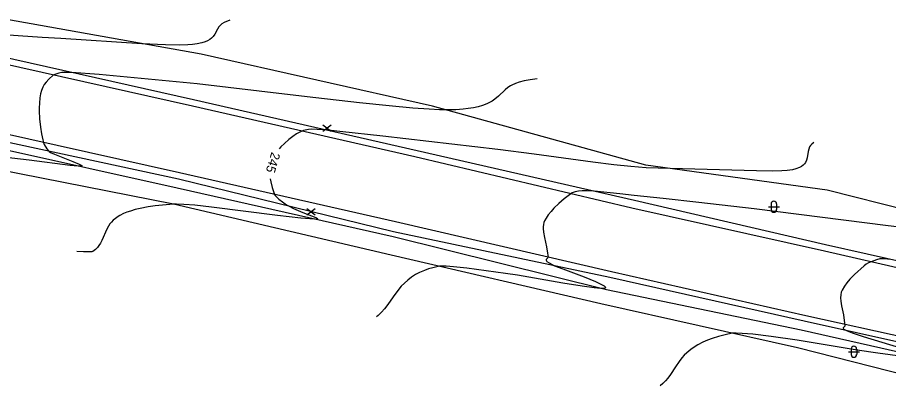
# Model space of a CAD drawing. Extents: x -593772 to -592667, y -1183541 to -1183371.
# Drawn here: x -593242.3 to -593163.4, y -1183452.7 to -1183418.4 of the extents above; entities that cross this region are included whole.
import ezdxf

# ---------------------------------------------------------------- set-up
doc = ezdxf.new("R2010")
doc.units = 0
for name, color, linetype in [('bez obruby', 7, 'Continuous'), ('hlavni vrstevnice', 7, 'Continuous'), ('popis ploch', 7, 'Continuous'), ('svisle dopravni znaceni', 7, 'Continuous'), ('terenni hrany', 7, 'Continuous'), ('vrstevnice', 7, 'Continuous')]:
    doc.layers.add(name, color=color, linetype=linetype)

msp = doc.modelspace()

# ---------------------------------------------------------------- linework, layer by layer
at = {"layer": 'bez obruby'}
for p, q in [((-593226.44, -1183426.4), (-593245.4, -1183422.16)), ((-593206.31, -1183430.99), (-593226.44, -1183426.4)), ((-593227.63, -1183432.42), (-593247, -1183428.11)), ((-593186.66, -1183435.62), (-593206.31, -1183430.99)), ((-593208.05, -1183436.87), (-593227.63, -1183432.42)), ((-593169.2, -1183439.54), (-593186.66, -1183435.62)), ((-593188.48, -1183441.41), (-593208.05, -1183436.87)), ((-593152.12, -1183443.4), (-593169.2, -1183439.54)), ((-593170.89, -1183445.38), (-593188.48, -1183441.41)), ((-593153.22, -1183449.3), (-593170.89, -1183445.38))]:
    msp.add_line(p, q, dxfattribs=at)
at = {"layer": 'hlavni vrstevnice'}
for points in [[(-593170.165, -1183429.693), (-593170.338, -1183429.83), (-593170.451, -1183429.951), (-593170.538, -1183430.079), (-593170.628, -1183430.278), (-593170.686, -1183430.494), (-593170.778, -1183431.067), (-593170.836, -1183431.284), (-593170.927, -1183431.483), (-593171.017, -1183431.61), (-593171.133, -1183431.73), (-593171.281, -1183431.842), (-593171.466, -1183431.944), (-593171.802, -1183432.074), (-593172.106, -1183432.147), (-593172.577, -1183432.218), (-593173.067, -1183432.252), (-593173.906, -1183432.269), (-593175.342, -1183432.254), (-593183.175, -1183432.038), (-593185.343, -1183431.971), (-593186.744, -1183431.866), (-593188.267, -1183431.707), (-593190.172, -1183431.472), (-593195.483, -1183430.73), (-593198.781, -1183430.317), (-593209.201, -1183429.094), (-593213.098, -1183428.678), (-593214.403, -1183428.548), (-593215.144, -1183428.492), (-593215.64, -1183428.484), (-593215.945, -1183428.512), (-593216.397, -1183428.6), (-593216.551, -1183428.652), (-593217.009, -1183428.895), (-593217.365, -1183429.126), (-593217.729, -1183429.409), (-593218.123, -1183429.758), (-593218.451, -1183430.081), (-593218.601, -1183430.254)], [(-593219.408, -1183432.96), (-593219.354, -1183433.256), (-593219.224, -1183433.76), (-593219.022, -1183434.384), (-593218.952, -1183434.488), (-593218.612, -1183434.801), (-593218.302, -1183435.059), (-593217.931, -1183435.318), (-593217.693, -1183435.463), (-593217.305, -1183435.655), (-593216.438, -1183436.02), (-593215.283, -1183436.486), (-593215.13, -1183436.573), (-593215.102, -1183436.61), (-593215.118, -1183436.63), (-593215.234, -1183436.644), (-593215.406, -1183436.636), (-593216.623, -1183436.526), (-593218.737, -1183436.285), (-593224.715, -1183435.542), (-593226.246, -1183435.374), (-593227.242, -1183435.286), (-593227.9, -1183435.255), (-593228.15, -1183435.26), (-593229.173, -1183435.349), (-593229.824, -1183435.424), (-593230.451, -1183435.516), (-593231.177, -1183435.653), (-593231.639, -1183435.766), (-593232.053, -1183435.888), (-593232.382, -1183436.003), (-593232.679, -1183436.127), (-593233.024, -1183436.303), (-593233.176, -1183436.392), (-593233.407, -1183436.553), (-593233.619, -1183436.732), (-593233.793, -1183436.911), (-593233.916, -1183437.061), (-593234.053, -1183437.261), (-593234.211, -1183437.542), (-593234.649, -1183438.554), (-593234.775, -1183438.79), (-593234.916, -1183439.005), (-593235.061, -1183439.186), (-593235.238, -1183439.366), (-593235.474, -1183439.559), (-593235.553, -1183439.582), (-593235.76, -1183439.597), (-593236.303, -1183439.581), (-593236.91, -1183439.551)]]:
    msp.add_lwpolyline(points, dxfattribs=at)
at = {"layer": 'popis ploch'}
for p, q in [((-593174.03, -1183435.25), (-593174.03, -1183435.75)), ((-593173.53, -1183435.25), (-593173.53, -1183435.75)), ((-593174.28, -1183435.5), (-593173.28, -1183435.5)), ((-593167.03, -1183448.64), (-593166.03, -1183448.64)), ((-593166.78, -1183448.39), (-593166.78, -1183448.89)), ((-593166.28, -1183448.39), (-593166.28, -1183448.89))]:
    msp.add_line(p, q, dxfattribs=at)
for centre, start, end in [((-593173.781, -1183435.25), 0, 180), ((-593173.781, -1183435.75), 180, 0), ((-593166.531, -1183448.39), 0, 180), ((-593166.531, -1183448.89), 180, 0)]:
    msp.add_arc(centre, 0.25, start, end, dxfattribs=at)
at = {"layer": 'svisle dopravni znaceni'}
for p, q in [((-593214.635, -1183428.641), (-593213.885, -1183428.079)), ((-593214.635, -1183428.079), (-593213.885, -1183428.641)), ((-593216.085, -1183436.221), (-593215.335, -1183435.659)), ((-593216.085, -1183435.659), (-593215.335, -1183436.221))]:
    msp.add_line(p, q, dxfattribs=at)
at = {"layer": 'terenni hrany'}
for p, q in [((-593225.65, -1183421.68), (-593244.32, -1183418.35)), ((-593226.34, -1183425.83), (-593245.24, -1183421.57)), ((-593204.71, -1183426.4), (-593225.65, -1183421.68)), ((-593206.09, -1183430.43), (-593226.34, -1183425.83)), ((-593185.39, -1183431.73), (-593204.71, -1183426.4)), ((-593227.72, -1183432.99), (-593247.27, -1183428.81)), ((-593227.84, -1183433.83), (-593247.47, -1183429.43)), ((-593186.39, -1183434.94), (-593206.09, -1183430.43)), ((-593228.15, -1183435.26), (-593248.06, -1183431.37)), ((-593168.95, -1183434), (-593185.39, -1183431.73)), ((-593208.24, -1183437.78), (-593227.72, -1183432.99)), ((-593208.26, -1183438.24), (-593227.84, -1183433.83)), ((-593150.18, -1183438.78), (-593168.95, -1183434)), ((-593208.44, -1183439.88), (-593228.15, -1183435.26)), ((-593169.09, -1183438.94), (-593186.39, -1183434.94)), ((-593188.63, -1183441.92), (-593208.24, -1183437.78)), ((-593188.95, -1183443.02), (-593208.26, -1183438.24)), ((-593151.87, -1183442.83), (-593169.09, -1183438.94)), ((-593189.45, -1183444.31), (-593208.44, -1183439.88)), ((-593171.04, -1183445.87), (-593188.63, -1183441.92)), ((-593171.32, -1183446.69), (-593188.95, -1183443.02)), ((-593171.65, -1183448.28), (-593189.45, -1183444.31)), ((-593153.34, -1183449.83), (-593171.04, -1183445.87)), ((-593153.53, -1183450.71), (-593171.32, -1183446.69)), ((-593154.23, -1183452.7), (-593171.65, -1183448.28))]:
    msp.add_line(p, q, dxfattribs=at)
at = {"layer": 'vrstevnice'}
for points in [[(-593223.05, -1183418.601), (-593223.58, -1183418.822), (-593223.775, -1183418.938), (-593223.933, -1183419.074), (-593224.056, -1183419.215), (-593224.184, -1183419.417), (-593224.433, -1183419.882), (-593224.574, -1183420.079), (-593224.71, -1183420.221), (-593224.876, -1183420.348), (-593225.089, -1183420.468), (-593225.309, -1183420.562), (-593225.609, -1183420.655), (-593226.024, -1183420.745), (-593226.438, -1183420.806), (-593226.859, -1183420.842), (-593227.627, -1183420.863), (-593228.88, -1183420.834), (-593231.022, -1183420.736), (-593238.374, -1183420.257), (-593240.049, -1183420.161), (-593242.232, -1183420.02), (-593244.774, -1183419.835)], [(-593195.232, -1183423.908), (-593195.866, -1183423.996), (-593196.395, -1183424.099), (-593196.843, -1183424.215), (-593197.175, -1183424.328), (-593197.503, -1183424.473), (-593197.625, -1183424.538), (-593197.881, -1183424.71), (-593198.116, -1183424.905), (-593198.734, -1183425.499), (-593199.042, -1183425.753), (-593199.295, -1183425.926), (-593199.552, -1183426.071), (-593199.792, -1183426.185), (-593200.172, -1183426.33), (-593200.559, -1183426.445), (-593200.991, -1183426.54), (-593201.467, -1183426.615), (-593201.917, -1183426.666), (-593202.587, -1183426.71), (-593203.492, -1183426.729), (-593204.072, -1183426.712), (-593204.99, -1183426.668), (-593206.49, -1183426.565), (-593208.638, -1183426.373), (-593211.322, -1183426.091), (-593215.276, -1183425.632), (-593217.598, -1183425.352), (-593226.01, -1183424.371), (-593231.08, -1183423.879), (-593234.891, -1183423.532), (-593237.397, -1183423.344), (-593237.914, -1183423.329), (-593238.267, -1183423.349), (-593238.541, -1183423.396), (-593239.006, -1183423.54), (-593239.068, -1183423.577), (-593239.469, -1183423.946), (-593239.706, -1183424.204), (-593239.873, -1183424.429), (-593240.006, -1183424.663), (-593240.125, -1183424.957), (-593240.209, -1183425.262), (-593240.271, -1183425.629), (-593240.313, -1183426.113), (-593240.331, -1183426.548), (-593240.332, -1183426.804), (-593240.288, -1183427.536), (-593240.214, -1183428.291), (-593240.121, -1183428.891), (-593239.999, -1183429.45), (-593239.933, -1183429.692), (-593239.866, -1183429.875), (-593239.651, -1183430.245), (-593239.508, -1183430.418), (-593239.438, -1183430.485), (-593239.302, -1183430.575), (-593238.934, -1183430.75), (-593238.049, -1183431.103), (-593237.291, -1183431.394), (-593236.719, -1183431.632), (-593236.528, -1183431.735), (-593236.477, -1183431.78), (-593236.472, -1183431.804), (-593236.492, -1183431.821), (-593236.57, -1183431.836), (-593236.785, -1183431.832), (-593237.513, -1183431.766), (-593241.234, -1183431.29), (-593249.932, -1183430.288)], [(-593159.736, -1183437.654), (-593163.43, -1183437.222), (-593175.564, -1183435.703), (-593180.566, -1183435.115), (-593183.794, -1183434.761), (-593186.427, -1183434.498), (-593187.721, -1183434.339), (-593190.072, -1183434.101), (-593190.696, -1183434.059), (-593191.153, -1183434.057), (-593191.482, -1183434.089), (-593191.77, -1183434.154), (-593191.956, -1183434.207), (-593192.061, -1183434.252), (-593192.765, -1183434.791), (-593193.252, -1183435.209), (-593193.701, -1183435.641), (-593193.967, -1183435.926), (-593194.229, -1183436.242), (-593194.421, -1183436.525), (-593194.549, -1183436.77), (-593194.61, -1183436.921), (-593194.662, -1183437.12), (-593194.686, -1183437.328), (-593194.688, -1183437.487), (-593194.659, -1183437.819), (-593194.571, -1183438.276), (-593194.369, -1183439.141), (-593194.273, -1183439.714), (-593194.236, -1183440.076), (-593194.249, -1183440.128), (-593194.399, -1183440.291), (-593194.408, -1183440.344), (-593194.377, -1183440.406), (-593194.334, -1183440.449), (-593194.145, -1183440.589), (-593193.664, -1183440.862), (-593192.886, -1183441.134), (-593190.954, -1183441.862), (-593189.933, -1183442.278), (-593189.382, -1183442.534), (-593189.155, -1183442.663), (-593189.05, -1183442.746), (-593189.009, -1183442.812), (-593189.024, -1183442.848), (-593189.079, -1183442.875), (-593189.243, -1183442.897), (-593189.468, -1183442.896), (-593190.051, -1183442.848), (-593191.144, -1183442.708), (-593192.909, -1183442.426), (-593197.007, -1183441.711), (-593198.075, -1183441.554), (-593201.605, -1183441.077), (-593202.806, -1183440.941), (-593203.464, -1183440.892), (-593203.907, -1183440.885), (-593204.063, -1183440.899), (-593204.675, -1183441.023), (-593205.051, -1183441.127), (-593205.438, -1183441.266), (-593205.873, -1183441.459), (-593206.235, -1183441.65), (-593206.595, -1183441.876), (-593206.95, -1183442.144), (-593207.252, -1183442.414), (-593207.537, -1183442.71), (-593207.857, -1183443.1), (-593208.253, -1183443.65), (-593208.751, -1183444.365), (-593209.051, -1183444.749), (-593209.319, -1183445.05), (-593209.618, -1183445.34), (-593209.78, -1183445.48)], [(-593163.191, -1183440.275), (-593163.783, -1183440.225), (-593164.093, -1183440.223), (-593164.181, -1183440.234), (-593164.478, -1183440.307), (-593165.208, -1183440.585), (-593165.415, -1183440.696), (-593165.615, -1183440.844), (-593166.49, -1183441.636), (-593166.891, -1183442.048), (-593167.176, -1183442.388), (-593167.394, -1183442.694), (-593167.602, -1183443.058), (-593167.675, -1183443.25), (-593167.728, -1183443.495), (-593167.745, -1183443.745), (-593167.729, -1183444.05), (-593167.662, -1183444.464), (-593167.482, -1183445.299), (-593167.355, -1183446.285), (-593167.36, -1183446.327), (-593167.498, -1183446.461), (-593167.509, -1183446.502), (-593167.486, -1183446.552), (-593167.396, -1183446.625), (-593167.135, -1183446.755), (-593166.69, -1183446.924), (-593165.688, -1183447.255), (-593162.302, -1183448.286)], [(-593162.141, -1183449.065), (-593164.364, -1183448.764), (-593166.221, -1183448.485), (-593171.661, -1183447.576), (-593174.019, -1183447.256), (-593175.674, -1183447.06), (-593176.639, -1183446.971), (-593177.188, -1183446.944), (-593177.504, -1183446.956), (-593177.565, -1183446.963), (-593178.194, -1183447.096), (-593178.8, -1183447.252), (-593179.372, -1183447.432), (-593179.782, -1183447.588), (-593180.21, -1183447.776), (-593180.658, -1183448.01), (-593180.992, -1183448.216), (-593181.292, -1183448.426), (-593181.656, -1183448.724), (-593181.897, -1183448.949), (-593182.109, -1183449.179), (-593182.367, -1183449.507), (-593182.705, -1183450.016), (-593183.142, -1183450.7), (-593183.387, -1183451.032), (-593183.589, -1183451.266), (-593183.825, -1183451.503), (-593184.069, -1183451.713)]]:
    msp.add_lwpolyline(points, dxfattribs=at)

# ---------------------------------------------------------------- texts
at = {"layer": 'hlavni vrstevnice'}
msp.add_text('245', height=0.8351, rotation=253.27328, dxfattribs=at).set_placement((-593219.277, -1183430.494))

doc.saveas('drawing.dxf')
